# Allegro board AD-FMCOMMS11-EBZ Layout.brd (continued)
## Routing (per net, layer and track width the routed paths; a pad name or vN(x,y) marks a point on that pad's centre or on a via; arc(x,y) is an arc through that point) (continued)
SVDD12_DAC: length 54.2
  TOP w0.203: U1.K14 v2(54.48,23.34) U1.J14 ; U1.R1 57.22,16.53 v2(57.23,16.53)
  TOP w0.254: U1.M13 U1.M14 v2(56.22,23.34) ; v2(56.72,19.34) U1.P7 ; U1.K2 v2(54.48,17.34) U1.J2 ; U1.N2 v2(55.97,17.34) U1.M2 v2(55.72,17.84) ; U1.P3 v2(56.72,18.1) U1.P4 ; U1.P13 v2(56.72,22.6) U1.P12 ; U1.P9 v2(56.72,21.34)
  L3_SIGNAL w0.508: v3(59.82,16.72) v3(59.31,16.72) v3(58.8,16.72) 58.54,16.72 v3(58.29,16.47) 58.29,14.94 56.9,13.55 52.83,13.55 51.56,12.28 48.26,12.28 46.61,13.93 46.61,16.22 44.96,17.87 37.72,17.87 v3(36.96,18.63)
  BOTTOM w0.203: C133.1 56.22,23.73 v2(56.22,23.34)
  BOTTOM w0.254: v2(54.48,23.34) 54.48,23.76 C132.1 ; C115.1 57,17.82 v2(56.72,18.1) ; v2(56.72,22.6) 56.86,22.6 C121.1 ; C136.1 55.97,16.88 v2(55.97,17.34) ; v2(56.72,21.34) 57.01,21.34 C108.1
  BOTTOM w0.305: v2(57.23,16.53) C130.1 57.96,16.53 ; C111.1 56.72,19.47 v2(56.72,19.34) ; v3(36.96,18.63) 36.96,20.03 36.07,20.92 R45.1 ; v2(54.48,17.34) 54.48,17.01 C134.1
  BOTTOM w0.406: C335.1 57.52,14.97 ; C335.1 58.18,14.31 ; C335.1 57.52,13.65
  BOTTOM w0.508: C122.1 59.83,18.4 ; C122.1 59.83,17.08 ; C122.1 59.17,17.74
  BOTTOM w0.635: 58.57,15.58 C106.1 ; C106.1 59.47,16.53 ; C106.1 59.47,14.63 ; C311.1 59.47,14.25 ; C311.1 58.57,13.3 ; C311.1 59.47,12.34
  BOTTOM w0.762: 58.23,11.75 E9.2 59.16,10.76
  vias: v2(57.22,23.84)
SVDD12_EN: length 121
  TOP w0.203: U21.3 55.26,1.6 v3(54.61,2.25)
  L3_SIGNAL w0.203: v3(48.64,31.27) 49.42,31.27 49.91,31.76 60.38,31.76 61.7,30.44 64.01,30.44 v3(65.28,29.17)
  L10_SIGNAL w0.203: v3(65.28,29.17) 66.29,28.15 66.29,19.39 v3(68.96,16.72) 68.96,14.82 72.9,10.88 72.9,3.77 72.01,2.88 58.42,2.88 57.78,2.25 v3(54.61,2.25) ; v1(51.43,38.19) 51.43,33.23 49.47,31.27 v3(48.64,31.27) 47.56,31.27 44.2,27.9 v1(38.23,27.9)
  BOTTOM w0.203: R89.1 v1(51.43,38.19) ; U9.C1 68.19,18.25 68.96,17.49 v3(68.96,16.72) ; v1(38.23,27.9) 37.72,27.39 31.24,27.39 29.46,25.61 23.75,25.61 22.73,24.6 22.73,21.93 23.1,21.56 23.75,21.56 24.02,21.3 ; 24.02,21.3 U22.8 ; 24.02,21.3 24.01,21.3 R53.2
SVDD12PHY_DAC: length 15.8
  BOTTOM w0.305: v2(55.22,17.84) 55.22,19.16 55.4,19.33 ; 55.22,22.34 v2(55.22,22.84) 55.52,22.84 55.72,23.04 55.72,25.38 C340.1
  BOTTOM w0.508: 55.4,19.33 55.4,22.16 55.22,22.34
  BOTTOM w0.635: C313.1 59.94,26.5 59.31,25.87 55.99,25.87 C340.1
  BOTTOM w0.762: E6.2 58.04,27.33 C313.1
VDD5_361: length 14.3
  TOP w0.508: TP22.1 C164.1
  TOP w0.635: 39.74,63.69 39.74,63.82 39.71,63.84 ; 39.74,63.69 C164.1 ; 39.74,63.69 C157.1 ; v3(46.86,61.68) 46.61,61.94 TP22.1
  TOP w0.762: C157.1 39.71,63.84 39.81,63.94 E22.2
  BOTTOM w0.305: U19.4 45.47,61.3 45.78,60.98 C333.1 v3(46.86,61.68)
VDD_1119: length 10.4
  TOP w0.254: U25.2 26.81,52.15 26.54,52.41 26.54,52.54 26.29,52.79 25.97,52.79 R137.1
  TOP w0.305: C337.1 25.7,53.62 C338.1 25.02,53.11 ; 25.35,52.86 R137.1
  BOTTOM w0.508: C238.1 23.81,50.18 ; C238.1 23.15,49.52 ; C238.1 23.15,50.84
  BOTTOM w0.635: C233.1 23.37,49.1 ; C233.1 24.28,48.15 ; C233.1 23.37,47.2 ; 26.03,48.2 E27.2 25.04,47.27
  vias: v3(23.75,52.92) v3(24.38,52.92)
VDDA12_DAC: length 9.4
  TOP w0.305: TP1.1 v3(52.07,29.81)
  BOTTOM w0.305: E7.2 v3(52.07,29.81) ; v2(50.72,22.84) v2(50.72,23.34) 50.74,23.36 C135.1 50.74,24.9 C93.1
  BOTTOM w0.508: C93.1 50.66,26.48 C84.1
  BOTTOM w0.635: C84.1 50.8,26.92 50.8,29.74 E7.2
VDDA25_DAC: length 19.9
  TOP w0.305: TP4.1 v3(31.88,14.57)
  TOP w0.508: C1.1 39.37,22.83 v3(39.37,23.33) ; v3(43.05,20.15) v3(42.54,20.15) v4(41.91,20.15) v4(41.53,20.15) T1.2 v4(41.02,20.15) v3(40.39,20.15) 39.36,20.15 C3.1 ; v3(43.05,18.88) v4(42.67,18.88) v4(42.04,18.88) T1.1 v4(41.4,18.88) v4(40.89,18.88) v4(40.39,18.88) 39.5,18.88 39.37,18.76 ; v3(47.69,14.25) 47.69,13.77 C185.1 ; v3(47.83,15.84) C79.1
  BOTTOM w0.254: C109.1 49.47,21.74 v2(49.78,21.42) ; v2(49.78,18.88) 49.47,18.57 C112.1 ; v2(50.72,19.34) 50.72,19.63 C113.1 ; v2(50.72,20.84) 50.72,20.68 C114.1
  BOTTOM w0.508: R48.1 v3(36.2,18.63) ; 33.41,14.03 C96.1 32.75,14.69 ; v3(43.05,20.15) v3(42.54,20.15)
  BOTTOM w0.635: C87.1 33.06,13.74 ; C87.1 32.16,12.79 ; C87.1 33.06,11.83 ; 33.06,11.45 E12.2 32.16,10.5
  vias: v2(50.22,17.34) v2(50.72,22.34) v2(50.72,17.84) v2(51.22,23.84) v2(51.22,21.84) v2(51.22,18.34) v3(31.24,14.57) v3(31.24,13.93) v3(31.24,13.3) v3(31.88,13.93) v3(31.88,13.3) v3(39.37,19.39) v3(40.39,23.33) v3(42.54,23.2) v3(43.05,22.31) v3(43.05,21.42) v4(39.5,18.12) v4(39.88,17.61) v4(40.39,17.11) v4(41.02,23.33) v4(41.02,17.11) v4(41.53,23.33) v4(41.66,17.11) v4(42.04,23.33) v4(42.29,17.11) v4(42.93,17.11) v4(43.05,23.2) v4(43.05,20.79) v4(43.56,23.2) v4(43.56,17.11) v4(44.07,23.2) v4(44.2,17.11) v4(44.58,23.2) v4(44.83,17.11) v4(45.09,23.2) v4(45.34,17.11) v4(45.59,23.2) v4(45.97,17.11) v4(46.1,23.2) v4(46.61,23.2) v4(46.61,17.11) v4(47.12,23.2) v4(47.75,23.2) v4(47.88,17.23) v4(48.39,22.82) v4(48.39,17.49) v4(48.89,22.44) v4(48.89,17.87)
VDDA25_EN: length 30.4
  L10_SIGNAL w0.203: v3(34.67,1.87) 31.24,5.29 29.97,5.29 24.51,10.76 24.51,17.36 v3(24.13,17.74)
  BOTTOM w0.203: 23.75,20.39 23.1,20.39 22.86,20.15 22.86,19.01 v3(24.13,17.74) ; 23.75,20.39 25.13,20.39 25.53,20.8 U22.7 ; 23.75,20.39 R54.2 ; U7.7 35.06,2.25 v3(34.67,1.87)
VDDC12_DAC: length 15.5
  TOP w0.254: v2(52.72,16.84) v2(52.72,17.34) v2(52.72,17.84) ; v2(52.22,23.84) v2(52.72,23.84) v2(52.72,23.34) v2(52.72,22.84)
  TOP w0.305: TP3.1 v3(38.86,15.71)
  BOTTOM w0.203: v2(52.72,17.34) 52.25,17.34 C138.1 ; v2(52.72,17.34) v2(52.72,16.84) ; v2(52.72,17.34) v2(52.72,17.84)
  BOTTOM w0.254: C107.1 v2(52.29,21.3) ; C110.1 v2(52.2,18.88)
  BOTTOM w0.305: U28.11 40.51,14.33 ; U28.13 41.76,14.46 41.53,14.69 41.15,14.69 ; v2(52.72,23.84) 53.14,23.84 C137.1 ; 39,13.53 U28.9 39.51,14.33 ; U28.12 41.01,14.33 ; U28.10 40.01,14.33
  BOTTOM w0.508: C183.1 53.35,15.31 v3(53.21,15.45) 53.07,15.31 C184.1
  BOTTOM w0.635: 39.78,15.96 C341.1 40.68,15.01
  vias: v3(38.86,15.07) v3(39.5,15.71) v3(39.5,15.07)
VIN_N: length 2.8
  TOP w0.203: R63.2 45.52,52.74 45.88,52.38 U101.A10
VIN_P: length 2.8
  TOP w0.203: U101.A9 45.9,51.58 45.54,51.22 R62.2
3P3V_P1: length 22.2
  TOP w0.508: v3(94.28,9.03) 94.28,8.12 R40.2 ; v3(72.25,4.39) R30.2 73.52,3.39 R32.1
  TOP w1.016: 84.48,4.72 E3.1 ; E3.1 85.41,5.71 ; E3.1 85.41,3.73
  BOTTOM w0.305: 94.91,9.67 v3(94.28,9.03) ; 80.26,12.28 79.48,11.5 U6.18 79.99,10.85 ; 81.08,10.1 U6.19 80.23,10.61 ; 81.65,9.6 81.15,9.1 U6.21 ; 81.65,9.6 U6.20 ; 81.65,9.6 v3(81.66,9.61) ; 94.91,14.75 v1(94.3,14.44)
  BOTTOM w0.406: 94.91,12.21 v3(94.28,11.57) ; P1.C39 v3(96.82,11.57)
  BOTTOM w0.508: R28.1 84.07,9.36 84.2,9.49 v3(84.2,9.61)
  BOTTOM w0.762: 83.06,9.81 C56.2 ; C56.2 81.9,10.82 ; C56.2 84.21,10.82 ; 81.22,13.08 C57.2 80.26,12.28
  vias: v3(82.3,9.61) v3(82.93,9.61) v3(83.57,9.61) v3(85.09,6.56) v3(85.09,5.93) v3(85.09,3.52) v3(85.09,2.88) v3(85.72,6.56) v3(85.72,5.93) v3(85.72,3.52) v3(85.72,2.88)
3P3VAUX_P1: length 62.3
  TOP w0.305: U26.16 103.52,10.64 v3(103.25,10.37) ; v3(102.81,20.15) 102.81,20.94 R34.2 ; U26.10 103.52,15.69 103.11,16.1 C129.2 ; U26.17 v3(104.02,10.37) ; R64.2 v3(104.15,3.53)
  TOP w0.508: C154.1 v3(102.81,20.15) ; v3(102.73,31.7) 102.98,31.44 C83.1 102.98,30.17 102.87,30.06 U8.8
  TOP w0.635: C154.1 103.11,18.58 C129.2
  L10_SIGNAL w0.305: v3(104.15,3.53) 104.65,4.02 104.65,9.75 v3(104.02,10.37)
  L10_SIGNAL w0.508: v3(103.25,10.37) v3(104.02,10.37) ; v3(103.25,10.37) 103.25,11.74 102.81,12.19 v3(102.81,20.15) 104.13,20.15 105.03,21.05 105.03,26 102.73,28.29 v3(102.73,31.7) ; v3(103.25,10.37) 100.91,10.37 100.51,10.78 100.51,11.85 99.63,12.72 99.63,14.86 99.1,15.38 94.87,15.38 93.73,16.53 93.73,18.64 v1(94.28,19.19)
  BOTTOM w0.508: 94.91,19.83 v1(94.28,19.19)
+INTERNAL_CLK: length 4.1
  BOTTOM w0.305: Y1.4 24.74,36.79 R33.2 R73.1 28.32,36.79 JP1.1
-INTERNAL_CLK: length 4.1
  BOTTOM w0.305: JP2.1 28.32,34.25 R12.1 R10.2 24.74,34.25 Y1.5
ADC_CLK_N: length 2.8
  TOP w0.203: U101.G14 52.81,56.02 53.62,56.83 R70.2 53.62,57.99 C201.2
ADC_CLK_P: length 2.8
  TOP w0.203: U101.F14 52.01,56.02 51.21,56.83 R69.1 51.21,58.04 C202.2
ARST: length 1.9
  TOP w0.305: U101.L9 v1(56.01,51.83)
  BOTTOM w0.203: v1(56.01,51.83) 56.45,51.4 56.81,51.4 R104.1
BST_2165: length 2.8
  TOP w0.203: C61.2 75.44,9.14 75.44,8.98 v3(75.06,8.6)
  BOTTOM w0.203: v3(75.06,8.6) 75.06,8.6 U6.9
BST_2384: length 3.7
  TOP w0.203: C39.2 78.57,32.98 v3(79.12,32.98)
  BOTTOM w0.305: U2.15 78.99,32.85 v3(79.12,32.98)
CSB1119: length 97
  TOP w0.203: v3(33.15,53.81) 33.15,53.3 31.49,51.65 U25.16 ; U23.13 107.04,53.28 v3(108.08,54.32)
  L3_SIGNAL w0.203: v3(33.15,53.81) 33.7,54.36 33.7,57.17 35.17,58.63 39.75,58.63 43.49,62.37 69.78,62.37 71.37,63.97 80.9,63.97 81.91,64.98 86.36,64.98 88.65,62.7 88.65,61.43 90.93,59.14 95.76,59.14 99.31,62.7 v3(103.38,62.7)
  L10_SIGNAL w0.203: v3(108.08,54.32) 108.08,57.49 103.38,62.19 v3(103.38,62.7)
CSB1119_FMC: length 23.7
  TOP w0.203: v3(102.62,54.19) 103.25,54.19 103.72,53.72 U23.2
  L10_SIGNAL w0.203: v3(102.62,54.19) 96.39,54.19 93.22,51.01 93.22,48.47 92.33,47.58 92.33,43.19 91.12,41.98 v1(90.54,41.98)
  BOTTOM w0.127: P1.G15 v1(90.54,41.98)
CSB4355: length 95.2
  TOP w0.203: v3(108.08,52.79) 108.07,52.78 U23.12
  L3_SIGNAL w0.203: v3(108.08,52.79) 107.19,53.68 100.23,53.68 100.1,53.81 65.53,53.81 61.47,57.87 49.28,57.87 48.01,56.6 v3(36.83,56.6)
  L10_SIGNAL w0.203: v3(36.83,56.6) 36.83,49.49 36.45,49.11 36.45,47.46 36.96,46.95 36.96,40.6 v1(36.45,40.09)
  BOTTOM w0.203: U18.3 37.35,38.81 36.45,39.71 v1(36.45,40.09)
CSB4355_FMC: length 23.3
  TOP w0.203: v3(102.62,53.17) 103,52.78 U23.3
  L10_SIGNAL w0.203: v1(90.48,39.53) 90.49,39.53 92.33,41.36 92.33,42.25 95.76,45.68 97.03,45.68 97.92,46.57 100.87,46.57 102.62,48.32 v3(102.62,53.17)
  BOTTOM w0.127: P1.G16 v1(90.48,39.53)
CSB5240: length 146.7
  TOP w0.203: v3(108.08,51.27) 107.06,52.28 U23.11
  TOP w0.229: U16.29 16,19.9 v3(15.75,20.15)
  L3_SIGNAL w0.203: v3(22.35,54.19) 27.56,59.4 37.72,59.4 38.1,59.78 39.82,59.78 43.56,63.52 54.29,63.52 54.86,64.1 70.66,64.1 71.17,64.6 78.74,64.6 79.76,65.62 86.49,65.62 89.15,62.95 89.15,61.68 91.19,59.65 95.38,59.65 99.62,63.9 v3(103.32,63.9)
  L10_SIGNAL w0.203: v3(108.08,51.27) 107.44,51.9 107.44,57.24 102.66,62.02 102.66,63.24 v3(103.32,63.9) ; v3(15.75,20.15) 16.64,21.04 16.64,41.62 23.24,48.22 23.24,53.3 v3(22.35,54.19)
CSB5240_FMC: length 11.1
  TOP w0.203: v3(102.11,51.9) 102.49,52.28 U23.4
  L10_SIGNAL w0.203: v3(102.11,51.9) 101.15,50.94 98.61,50.94 96.52,48.86 96.52,47.15 v1(96.5,47.13)
  BOTTOM w0.203: P1.C10 v1(96.5,47.13)
CSB9162: length 83.4
  TOP w0.203: U24.11 107.82,45.43 108.08,45.17 v3(108.08,44.54) ; U1.G15 53.22,24.08 52.32,24.98 v1(52.32,25.49)
  L3_SIGNAL w0.203: v1(52.32,25.49) 52.52,25.29 53.77,25.29 54.88,26.4 59.92,26.4 63.25,23.07 75.82,23.07 77.6,21.3 91.68,21.3 93.26,22.88 93.26,24.27 95.42,26.43 98.34,26.43 98.85,25.92 101.01,25.92 101.9,25.04 103.69,25.04 v3(104.27,25.61)
  BOTTOM w0.203: v3(104.27,25.61) 104.27,26.76 107.23,29.72 107.23,35.35 107.19,35.39 107.19,38.57 108.08,39.46 v3(108.08,44.54)
CSB9162_FMC: length 13.3
  TOP w0.203: v3(102.49,45.17) 102.74,45.43 U24.4
  L3_SIGNAL w0.203: v3(102.49,45.17) 101.78,45.88 v1(99.82,45.88)
  BOTTOM w0.203: P1.G12 91.76,45.88 v1(99.82,45.88)
CSB9625: length 62.7
  TOP w0.203: U23.10 106.93,51.78 107.19,51.52 107.19,50.63 v3(108.08,49.74) ; U101.G4 v1(53.21,47.98)
  L3_SIGNAL w0.203: v3(108.08,49.74) 108.08,50.51 106.05,52.54 100.36,52.54 99.56,53.33 60.1,53.33 56.13,49.36 54.6,49.36 v1(53.21,47.98)
CSB9625_FMC: length 11.7
  TOP w0.203: v3(102.11,50.76) 103.13,51.78 U23.5
  L10_SIGNAL w0.203: v1(95.87,47.13) 95.87,46.79 96.11,46.54 96.8,46.54 97.1,46.85 97.1,47.79 98.93,49.62 100.97,49.62 v3(102.11,50.76)
  BOTTOM w0.203: P1.C11 v1(95.87,47.13)
DAC_CLK_N: length 2.4
  TOP w0.127: U1.D1 51.72,16.58 51.6,16.45 51.6,14.88 C190.2
DAC_CLK_P: length 2.4
  TOP w0.127: U1.C1 51.22,16.58 51.34,16.45 51.34,14.88 C191.2
DAC_OUT_N: length 0.3
  TOP w0.229: U1.A7 49.91,19.77
DAC_OUT_P: length 0.3
  TOP w0.229: U1.A8 49.91,20.41
DIVCLK_N: length 36.8
  TOP w0.127: v1(75.23,55.31) 74.96,55.59 60.22,55.59 59.69,55.05 58.69,55.05 U101.P13 ; v1(80.14,54.32) 80.64,54.32 80.76,54.44 92.09,54.44 93,53.53 93.34,53.53 C240.1
  BOTTOM w0.127: v1(75.23,55.31) 75.51,55.59 79.25,55.59 80.14,54.69 v1(80.14,54.32)
DIVCLK_P: length 37.3
  TOP w0.127: v1(75.23,56.12) 74.96,55.84 63.47,55.84 63.17,56.14 62.86,56.14 62.56,55.84 62.25,55.84 61.95,56.14 61.64,56.14 61.34,55.84 61.03,55.84 60.73,56.14 60.42,56.14 59.58,55.31 58.69,55.31 U101.P14 ; C239.1 93.34,53.81 93.08,53.81 92.19,54.7 80.78,54.7 80.65,54.82 v1(80.64,54.82)
  BOTTOM w0.127: v1(80.64,54.82) 80.37,54.82 79.35,55.84 75.51,55.84 v1(75.23,56.12)
DOUTA_N: length 53.5
  TOP w0.127: U101.P10 58.47,52.44 59.03,52.44 59.18,52.28 59.44,52.28 59.56,52.41 59.56,52.65 59.44,52.77 59.44,53.04
  TOP w0.254: 59.44,53.04 60.08,53.68 60.58,53.68 60.85,53.41 61.19,53.41 61.47,53.68 61.98,53.68 62.23,53.43 62.61,53.43 62.86,53.68 63.37,53.68 63.63,53.43 64.13,53.43 64.39,53.68 64.77,53.68 65.02,53.43 65.53,53.43 65.79,53.68 76.59,53.68 79.77,56.86 92.16,56.86 94.75,59.45 99,59.45 100.63,57.81 100.63,54.68 99.92,53.97 97.99,53.97 C223.1
DOUTA_P: length 54.4
  TOP w0.127: 59.12,53.36 59.1,53.35 59.1,53.26 58.61,52.77 58.29,52.77 U101.N10
  TOP w0.254: C222.1 97.99,53.52 100.11,53.52 101.09,54.49 101.09,58 99.19,59.9 94.56,59.9 91.97,57.31 79.58,57.31 76.4,54.14 59.89,54.14 59.12,53.36
DOUTB_N: length 40.6
  TOP w0.127: 60.41,52.05 60.39,52.03 60.3,52.03 60.12,51.85 59.85,51.58 U101.P9
  TOP w0.254: 60.41,52.05 60.64,52.28 60.93,52.28 61.13,52.09 61.51,52.09 61.71,52.28 77.23,52.28 80.4,55.46 93.09,55.46 93.69,56.06 96.93,56.06 C209.1
DOUTB_P: length 41.5
  TOP w0.127: 60.09,52.38 60.07,52.35 60.07,52.27 59.71,51.91 58.95,51.91 58.88,51.98 58.29,51.98 U101.N9
  TOP w0.254: C208.1 96.93,56.51 93.5,56.51 92.9,55.92 80.21,55.92 77.04,52.74 60.45,52.74 60.09,52.38
DOUTC_N: length 40.8
  TOP w0.127: 61.17,50.94 61.14,50.94 61.08,51 60.86,51 60.72,50.86 58.5,50.86 U101.P8
  TOP w0.254: 61.17,50.94 78.29,50.94 80.78,53.43 91.61,53.43 94.31,50.72 96.93,50.72 C211.1
DOUTC_P: length 41.7
  TOP w0.127: 61.17,51.4 61.14,51.4 61.08,51.33 60.72,51.33 60.58,51.19 58.29,51.19 U101.N8
  TOP w0.254: C210.1 96.93,51.18 94.5,51.18 91.8,53.88 80.59,53.88 78.1,51.4 61.17,51.4
DOUTD_N: length 40.5
  TOP w0.127: U101.P7 58.51,50.08 58.91,50.08 59.41,49.58 59.51,49.58 59.55,49.54 59.55,49.53
  TOP w0.254: C213.1 96.93,45.64 86.53,45.64 82.64,49.53 59.55,49.53
DOUTD_P: length 41.4
  TOP w0.127: U101.N7 58.04,50.41 59.05,50.41 59.33,50.13 59.53,49.93 59.71,49.93 59.76,49.98
  TOP w0.254: 59.76,49.98 82.83,49.98 86.71,46.1 96.93,46.1 C212.1
DOUTE_N: length 39.5
  TOP w0.127: U101.P5 58.81,48.38 58.88,48.45 59.64,48.45 59.88,48.21 60.36,48.21 60.42,48.14 60.45,48.14
  TOP w0.254: 60.45,48.14 81.99,48.14 85.8,44.33 91.64,44.33 92.88,43.1 95.66,43.1 C219.1
DOUTE_P: length 40.4
  TOP w0.127: 60.45,48.6 60.42,48.6 60.36,48.54 60.02,48.54 59.78,48.78 58.22,48.78 U101.N5
  TOP w0.254: C218.1 95.66,43.56 93.06,43.56 91.83,44.79 91.32,44.79 85.99,44.79 82.18,48.6 60.45,48.6
DOUTF_N: length 41.5
  TOP w0.127: 59.81,47.08 59.8,47.1 59.8,47.18 59.74,47.24 59.41,47.58 U101.P4
  TOP w0.254: C215.1 90.49,40.52 89.16,41.85 86.25,41.85 81.28,46.82 60.07,46.82 59.81,47.08
DOUTF_P: length 42.4
  TOP w0.127: U101.N4 58.19,47.97 59.49,47.97 60.04,47.41 60.13,47.41
  TOP w0.254: C214.1 96.89,40.98 90.68,40.98 89.35,42.31 86.44,42.31 81.47,47.28 60.26,47.28 60.13,47.41
DOUTG_N: length 40.9
  TOP w0.127: 60.5,45.45 60.49,45.45 60.42,45.52 60.14,45.52 58.88,46.78 U101.P3
  TOP w0.254: 60.5,45.45 80.62,45.45 88.05,38.02 95.66,38.02 C221.1
DOUTG_P: length 41.9
  TOP w0.127: 60.5,45.91 60.45,45.85 60.27,45.85 58.94,47.18 58.2,47.18 U101.N3
  TOP w0.254: 60.5,45.91 80.81,45.91 88.24,38.48 95.66,38.48 C220.1
DOUTH_N: length 43.6
  TOP w0.127: 59.77,44.74 59.74,44.76 59.74,44.85 58.62,45.98 U101.P2
  TOP w0.254: C217.1 96.93,35.48 87.53,35.48 86.46,36.55 86.46,37.57 80,44.03 60.48,44.03 59.77,44.74
DOUTH_P: length 44.5
  TOP w0.127: U101.N2 58.03,46.39 58.67,46.39 59.98,45.09 60.07,45.09 60.09,45.06
  TOP w0.254: C216.1 96.93,35.94 87.72,35.94 86.92,36.74 86.92,37.76 80.19,44.49 60.67,44.49 60.09,45.06
DRST: length 2.5
  TOP w0.305: U101.M13 v1(56.56,55.03)
  BOTTOM w0.305: R103.2 56.01,55.59 v1(56.56,55.03)
DRVDD1P3_ADC: length 13.5
  TOP w0.305: TP11.1 v3(65.28,60.03) ; U101.N1 v1(58.01,44.78) U101.P1 58.41,45.17 v1(58.8,44.78) ; v1(58.8,49.18) U101.P6 v1(58.01,49.18) U101.N6 ; U101.P11 v1(58,53.18) U101.N11 v1(57.21,53.18) U101.M11
  BOTTOM w0.305: C271.1 57.98,44.74 v1(58.01,44.78) ; v1(57.21,53.18) 56.97,53.18 C276.1
  BOTTOM w0.508: C235.1 63.77,60.67 ; C235.1 63.11,60.01 ; C235.1 63.11,61.33 ; 63.59,59.71 C230.1 64.49,58.76
  BOTTOM w0.762: 66.48,58.53 E24.2 ; E24.2 65.56,59.52 ; E24.2 66.48,60.51
  vias: v3(64.01,60.03) v3(64.64,60.03) v3(65.28,59.4)
DRVDD2P5_ADC: length 11.9
  TOP w0.305: U101.N13 v1(57.9,55.07) 57.61,55.35 U101.N14 v1(58.01,55.98)
  TOP w0.508: TP18.1 58.17,42.23 ; TP18.1 58.17,40.75 ; TP18.1 58.9,41.49 ; C254.1 59.96,42.15 ; C254.1 59.3,41.49 ; C254.1 59.96,40.83
  TOP w0.635: C251.1 59.22,40.54 ; C251.1 58.32,39.58 ; C251.1 59.22,38.63 ; 58.93,38.29 E28.2 57.94,37.36
  BOTTOM w0.305: C260.1 57.98,56.02 v1(58.01,55.98) 57.98,55.94 C263.1 57.98,55.14 v1(57.9,55.07)
  vias: v3(58.04,43.01) v3(58.04,42.38) v3(58.69,43.01) v3(58.67,42.38)
DSYNC_P1_N: length 11.8
  TOP w0.127: v1(89.48,50.94) 89.69,51.15 89.69,51.51 89.55,51.65 89.23,51.65 88.98,51.4 88.72,51.4 88.47,51.65 88.21,51.65 87.96,51.4 87.71,51.4 87.45,51.65 81.84,51.65 v1(81.55,51.36)
  BOTTOM w0.127: R125.1 80.3,51.65 81.26,51.65 v1(81.55,51.36) ; P1.H8 v1(89.48,50.94)
DSYNC_P1_P: length 11.8
  TOP w0.127: v1(81.55,52.17) 81.82,51.9 89.65,51.9 89.94,51.61 89.94,51.19 v1(90.19,50.94)
  BOTTOM w0.127: R123.1 80.3,51.9 81.29,51.9 v1(81.55,52.17) ; P1.H7 v1(90.19,50.94)
DUT_DSYNC_N: length 26.5
  TOP w0.254: U101.L3 v1(56.41,46.38)
  BOTTOM w0.127: v1(56.41,46.38) 56.41,46.97 57.03,47.59 68.2,47.59 72.45,51.84 78.21,51.84 78.59,51.46 R124.2 78.88,51.65 79.21,51.65 R125.2
DUT_DSYNC_P: length 26.6
  TOP w0.254: U101.L4 v1(55.61,47.18)
  BOTTOM w0.127: v1(55.61,47.18) 56.26,47.18 56.92,47.84 68.09,47.84 72.35,52.09 R124.1 78.88,51.9 79.21,51.9 R123.2
FB_2384: length 4.7
  TOP w0.254: v3(72.77,31.46) 71.97,31.46 R15.2 R16.2
  BOTTOM w0.254: v3(72.77,31.46) 73.42,31.85 U2.2
FPGA_CLK_N: length 78.2
  TOP w0.127: v1(85.98,33.74) 86.26,33.46 95.05,33.46 C34.1 ; T6.4 23.88,35.14 24.19,34.82 24.19,34.19 24.38,34 25.68,34 26.95,35.27 27.43,35.27 v1(27.69,35.52)
  L3_SIGNAL w0.127: v1(85.98,33.74) 85.72,33.49 84.71,33.49 82.17,30.95 71.99,30.95 71.22,31.71 71.01,31.71 66.29,31.71 63.63,34.38 63.42,34.38 41.15,34.38 39.75,32.98 31.22,32.98 28.81,35.39 27.81,35.39 v1(27.69,35.52)
FPGA_CLK_P: length 78.2
  TOP w0.127: T6.6 23.88,32.6 24.19,32.92 24.19,33.55 24.38,33.74 25.78,33.74 27.05,35.01 27.56,35.01 v1(27.69,34.89) ; C32.1 95.07,33.21 86.21,33.21 v1(85.98,32.98)
  L3_SIGNAL w0.127: v1(27.69,34.89) 27.94,35.14 28.7,35.14 31.11,32.73 39.86,32.73 41.25,34.12 63.52,34.12 66.19,31.46 71.12,31.46 71.88,30.69 82.27,30.69 84.81,33.23 85.72,33.23 v1(85.98,32.98)
GA0_P1: length 18.2
  TOP w0.203: v3(101.3,14.95) 102.19,14.95 102.5,14.63 U26.11 ; U8.2 v3(104.14,21.86)
  L3_SIGNAL w0.203: v1(96.59,16.65) 97.03,16.22 100.03,16.22 v3(101.3,14.95)
  L10_SIGNAL w0.203: v3(101.3,14.95) 101.6,15.25 101.6,20.42 103.04,21.86 v3(104.14,21.86)
  BOTTOM w0.254: P1.C34 v1(96.59,16.65)
GA1_P1: length 20.7
  TOP w0.203: v3(103.93,20.97) 102.87,22.03 U8.1 ; U26.13 101.68,13.3 v3(101.3,13.68)
  L10_SIGNAL w0.203: v3(101.3,13.68) 102.11,14.49 102.11,20.29 102.79,20.97 v3(103.93,20.97)
  BOTTOM w0.203: v3(101.3,13.68) 99.6,15.38 95.55,15.38 94.91,16.02
IRQ9162: length 68.9
  TOP w0.203: v3(103.17,33.67) 103.17,33.16 103.6,32.73 U14.8
  L3_SIGNAL w0.203: v2(53.22,16.84) 53.6,16.84 54.69,15.76 57.38,15.76 57.66,16.04 57.66,16.85 58.29,17.49 84.63,17.49 v1(86.34,19.19)
  L10_SIGNAL w0.203: v3(103.17,33.67) 95.43,33.67 91.82,30.06 91.82,28.15 86.34,22.67 v1(86.34,19.19) ; v1(53.59,12.91) 54.1,13.42 54.1,16.34 53.6,16.84 v2(53.22,16.84)
  BOTTOM w0.203: v1(53.59,12.91) CR5.C
IRQ9162_FMC: length 21.8
  TOP w0.203: v3(106.55,33.76) 106.03,33.23 U14.3
  L3_SIGNAL w0.203: v1(89.21,39.53) 89.92,38.82 91.16,38.82 94.84,35.14 103.5,35.14 104.89,33.76 v3(106.55,33.76)
  BOTTOM w0.203: P1.H16 v1(89.21,39.53)
IRQ9625: length 76.4
  TOP w0.203: U13.11 106.92,37.56 107.19,37.3 107.19,35.6 v3(106.72,35.14)
  TOP w0.254: U101.H5 v1(54.01,47.98)
  L3_SIGNAL w0.203: v1(54.01,47.98) 54.65,47.98 54.81,47.81 86.54,47.81 89.04,50.32 95.31,50.32 96.39,51.4 106.43,51.4 107.31,50.51 107.31,49.49 v3(108.08,48.73)
  L10_SIGNAL w0.203: v3(108.08,48.73) 106.43,47.08 106.43,42.12 106.68,41.87 106.68,40.47 106.43,40.22 106.43,35.44 v3(106.72,35.14)
  BOTTOM w0.203: R79.2 54.5,48.16 54.32,47.98 v1(54.01,47.98)
IRQ9625_FMC: length 14
  TOP w0.203: v3(102.74,36.54) 102.74,37.16 103.14,37.56 U13.6
  L10_SIGNAL w0.203: v3(102.74,36.54) 101.19,36.54 99.99,37.74 97.07,37.74 94.6,40.21 v1(94.6,42.05)
  BOTTOM w0.203: 94.91,41.42 v1(94.6,42.05)
MUX_OUT: length 89.8
  TOP w0.203: v3(106.17,40.73) 107.44,40.73 TP20.1 108.08,39.97 107.18,39.06 U13.14 ; R11.2 v1(33.27,44.03)
  L3_SIGNAL w0.203: v3(34.73,36.47) 36.32,38.06 40.64,38.06 41.91,36.79 51.43,36.79 52.39,37.74 63.82,37.74 65.79,39.71 85.34,39.71 85.85,40.22 94.73,40.22 95.24,40.73 101.09,40.73 102.23,39.58 105.03,39.58 v3(106.17,40.73)
  L10_SIGNAL w0.203: v3(34.73,36.47) 33.27,37.93 v1(33.27,44.03)
  BOTTOM w0.203: U18.30 34.94,36.27 v3(34.73,36.47)
MUXOUT_FMC: length 10.9
  TOP w0.203: v3(102.49,40.22) 102.49,39.46 102.88,39.06 U13.3
  L3_SIGNAL w0.203: v3(102.49,40.22) 101.35,41.36 95.89,41.36 95.23,42.02 v1(95.23,42.05)
  BOTTOM w0.305: 94.91,42.69 v1(95.23,42.05)
PG_1184: length 272.3
  TOP w0.203: R13.1 62.5,11.64 62.5,10.89 v3(62.48,10.88) ; v3(25.91,62.95) 25.91,63.84 25.65,64.1 U3.6 ; R75.1 87.76,66.7 87.76,65.62 89.83,63.54 v3(89.83,61.81) ; v3(66.8,29.11) R83.1 ; R31.1 69.66,3.39 R30.1 v3(71.26,4.39)
  L3_SIGNAL w0.203: v3(62.48,10.88) 61.72,11.64 59.94,11.64 58.55,10.25 v3(43.75,10.25) 41.78,12.22 41.78,15.58 40.51,16.85 30.1,16.85 v3(29.34,17.61) ; v3(76.2,28.66) 75.69,28.15 67.75,28.15 v3(66.8,29.11) ; v3(75.06,7.83) 73.28,7.83 71.26,5.81 v3(71.26,4.39) ; v3(89.83,61.81) 89.83,63.16 86.74,66.25 78.36,66.25 v3(77.34,65.24) ; v3(32.64,63.59) 32,62.95 v3(25.91,62.95) ; v3(76.2,23.96) 78.35,21.8 91.31,21.8 92.58,23.07 92.58,24.61 94.91,26.94 97.58,26.94 98.34,27.7 100.5,27.7 101.52,26.69 102.02,26.69 102.36,27.02 102.36,27.77 v3(101.73,28.41)
  L10_SIGNAL w0.203: v3(62.48,10.88) 62.48,7.96 63.88,6.56 69.09,6.56 v3(71.26,4.39) ; v3(75.06,7.83) 76.2,8.97 v3(76.2,23.96) v3(76.2,28.66) ; v3(29.34,17.61) 29.34,32.9 28.45,33.79 28.45,43.27 25.91,45.81 v3(25.91,62.95)
  BOTTOM w0.203: v3(62.48,10.88) 62.73,11.13 U5.3 ; v3(77.34,65.24) 77.03,64.92 R72.1 ; U22.6 28.81,20.3 29.34,19.77 v3(29.34,17.61) ; R76.1 34.29,54.95 32.64,56.6 v3(32.64,63.59) ; v3(89.83,61.81) 91.68,59.96 94.79,59.96 95.29,60.47 99.99,60.47 101.22,59.24 101.22,28.92 v3(101.73,28.41) ; U6.8 75.32,8.1 v3(75.06,7.83) ; R85.1 v3(43.75,10.25)
  BOTTOM w0.254: v3(76.2,28.66) U2.21
PG_C2M_P1: length 206.9
  L3_SIGNAL w0.203: v3(101.73,27.27) 100.78,28.21 92.39,28.21 86.49,22.31 78.74,22.31 v3(77.09,23.96) 75.44,25.61 66.17,25.61 v3(64.64,24.09) 61.47,27.27 58.47,27.27 57.84,27.9 54.02,27.9 52.11,26 35.05,26 34.16,25.11 v1(31.5,25.11)
  L10_SIGNAL w0.203: v3(77.22,29.04) 76.71,28.54 76.71,24.34 v3(77.09,23.96) 76.71,23.58 76.71,13.68 81.28,9.1 v3(81.28,7.83) ; v3(64.64,24.09) v3(64.64,16.72) ; v3(23.5,66.89) 26.67,63.71 26.67,50.76 30.35,47.08 30.35,40.32 32.18,38.5 32.18,36 31.5,35.32 31.5,31.43 31.88,31.05 31.88,25.49 v1(31.5,25.11)
  BOTTOM w0.203: R68.1 22.97,66.89 v3(23.5,66.89) ; U5.6 64.9,13.55 64.64,13.8 v3(64.64,16.72) ; R96.1 34.29,24.36 R95.1 34.24,24.28 R91.1 33.02,24.73 32.64,25.11 v1(31.5,25.11) ; v3(81.28,7.83) 81.01,8.1 U6.23 ; P1.D1 95.68,59.96 99.74,59.96 100.71,58.99 100.71,28.28 v3(101.73,27.27)
  BOTTOM w0.254: v3(77.22,29.04) 76.7,29.56 U2.20
PLL_REF_IN_N: length 1.5
  BOTTOM w0.254: U18.28 34.36,35.27 C186.2
PLL_REF_IN_P: length 1.5
  BOTTOM w0.254: C187.2 34.36,35.77 U18.29
PWDN: length 0.6
  TOP w0.254: U101.K4 v1(54.81,47.18)
RBIAS_EXT: length 1
  TOP w0.254: U101.J6 v1(54.81,48.78)
  BOTTOM w0.254: v1(54.81,48.78) 54.8,48.79 R110.2
REXT: length 1.2
  TOP w0.305: U101.M12 v1(57.21,54.38)
  BOTTOM w0.305: v1(57.21,54.38) 57.02,54.38 R109.2
RF_VDD_AMP_5: length 16.1
  TOP w0.305: C20.1 20.32,14.71 ; C20.1 19.66,14.04 ; C20.1 20.98,14.04 ; 17.05,17.7 U16.1 17.55,16.88 17.27,16.6 ; 18.36,13.87 C21.1 ; C21.1 18.92,14.38 ; C21.1 19.48,13.87 ; 21.21,14.46 L7.2 ; U16.25 17.12,21.9 17.55,22.34 U16.24 17.05,22.6 ; U16.25 16.54,21.9 16.19,22.25 C9.1 15.37,21.74 ; U16.25 16.85,22.41
  TOP w0.635: C102.1 16,16.19 ; C102.1 15.05,15.29 ; C102.1 16.96,15.29
  TOP w0.762: 12.6,15.52 E15.2 ; E15.2 13.59,16.45 ; E15.2 14.58,15.52
RST_B: length 1.2
  TOP w0.254: U101.K3 v1(55.61,46.38)
  BOTTOM w0.254: R101.2 55.88,45.98 55.61,46.25 v1(55.61,46.38)
RT_2165: length 7.1
  BOTTOM w0.203: U6.2 78.97,6.84 78.97,6.06 ; 78.97,6.06 78.99,6.06 79.12,5.93 79.76,5.93 80.28,5.41 C59.2 80.9,7.33 80.63,7.6 U6.24 ; 78.97,6.06 78.83,5.92 78.63,5.92 78.48,6.06 U6.3
SCL_P1: length 30.3
  TOP w0.203: v3(101.3,11.14) 101.81,11.64 102.3,11.64 102.5,11.85 U26.15 ; U8.6 v3(105.41,26.63)
  L3_SIGNAL w0.203: v3(105.41,26.63) 105.41,25.5 104.18,24.27 98.09,24.27 v3(96.82,23)
  L10_SIGNAL w0.203: v3(96.82,23) 101.09,18.73 101.09,15.71 100.71,15.33 100.71,13.29 100.96,13.04 101.47,13.04 101.85,12.66 101.85,11.69 v3(101.3,11.14)
  BOTTOM w0.203: P1.C30 v3(96.82,23)
SCLK_2P5: length 87.1
  TOP w0.203: U1.J13 54.22,22.46 v2(54.22,22.46) ; U24.13 106.92,46.43 v3(108.08,47.59)
  L3_SIGNAL w0.203: v3(105.92,21.3) 105.92,20.15 104.7,18.94 99.74,18.94 98.98,19.7 97.86,19.7 97.28,20.28 58.88,20.28 58.29,20.86 55.8,20.86 54.22,22.45 54.22,22.46 v2(54.22,22.46)
  L10_SIGNAL w0.203: v3(105.92,21.3) 106.55,20.66 107.19,20.66 107.57,21.04 107.57,33.62 107.95,34 107.95,36.03 107.44,36.54 107.44,38.71 108.12,39.39 108.12,43.48 107.54,44.05 107.54,47.05 v3(108.08,47.59)
SCLK_3P3: length 169.4
  TOP w0.127: U101.H4 53.21,47.18 53.21,43.9 v3(52.96,43.65)
  TOP w0.203: U13.13 108.07,38.56 v3(108.08,38.57) ; v3(32.26,53.81) 32.26,52.92 31.48,52.15 U25.17
  TOP w0.229: v3(15.75,18.63) 16.02,18.9 U16.31
  L3_SIGNAL w0.203: v1(36.45,40.85) 41.4,40.85 43.43,38.82 44.58,38.82 45.34,38.06 50.42,38.06 51.69,39.33 51.69,42.38 v3(52.96,43.65) 53.47,44.16 82.17,44.16 83.64,42.69 93.64,42.69 93.97,43.01 107.57,43.01 108.08,42.5 v3(108.08,38.57)
  L10_SIGNAL w0.203: v1(36.45,40.85) 35.94,40.35 35.94,39.84 36.26,39.52 36.64,39.52 36.96,39.2 36.96,38.06 35.81,36.92 35.81,36.08 32.94,33.2 32.94,25.42 33.4,24.95 33.4,19.9 29.97,16.47 v3(29.97,12.15)
  BOTTOM w0.203: v3(32.26,53.81) 31.11,52.67 31.11,50.38 30.1,49.36 30.1,43.27 32.13,41.24 36.07,41.24 v1(36.45,40.85) 35.94,40.35 35.94,38.7 36.35,38.29 U18.1 ; v3(29.97,12.15) 30.48,11.64 30.48,10.12 29.34,8.98 23.62,8.98 22.61,9.99 22.61,12.41 16.38,18.63 v3(15.75,18.63)
SCLK_FMC: length 21.2
  TOP w0.203: v3(102.5,38.58) 102.51,38.56 U13.4 ; U24.2 103.01,46.43 v3(102.49,46.95)
  L10_SIGNAL w0.203: v3(102.5,38.58) 103.12,39.2 103.12,40.85 102.62,41.36 102.62,42.67 103,43.05 103,46.44 v3(102.49,46.95) 100.71,45.17 100.71,44.28 99.57,43.14 97.59,43.14 v1(96.5,42.05)
  BOTTOM w0.203: P1.C14 v1(96.5,42.05)
SDA_P1: length 33.6
  TOP w0.203: U8.5 v3(106.68,26.63) ; U26.14 101.69,12.79 v3(101.3,12.41)
  L3_SIGNAL w0.203: v3(106.68,26.63) 106.05,26 106.05,25.12 104.44,23.51 100.04,23.51 98.9,22.37 96.18,22.37 v3(95.55,23)
  L10_SIGNAL w0.203: v3(101.3,12.41) 100.84,12.41 100.2,13.04 100.2,15.84 100.58,16.22 100.58,18.22 98.98,19.83 97.45,19.83 95.55,21.73 v3(95.55,23)
  BOTTOM w0.203: P1.C31 95.55,21.73 v3(95.55,23)
SDIO_2P5: length 64.2
  TOP w0.203: U14.9 103.09,32.23 v3(102.66,32.66)
  L3_SIGNAL w0.203: v3(100.84,24.91) 100.33,25.42 98.85,25.42 98.34,24.91 95.42,24.91 94.91,24.4 94.91,23.65 92.05,20.79 64.26,20.79 59.77,25.28 56.44,25.28 55.7,24.55 55.7,22.49 55.46,22.25 55.02,22.25 54.72,22.55 v2(54.72,22.84)
  L10_SIGNAL w0.203: v3(102.66,32.66) 102.03,32.66 100.84,31.47 v3(100.84,24.91)
SDIO_3P3: length 162.5
  TOP w0.127: U101.J4 54.01,47.18 v3(54.01,43.65)
  TOP w0.203: U25.18 31.1,52.65 31.37,52.92 v3(31.37,53.81) ; U13.12 107.06,38.06 v3(108.08,37.04) ; U16.30 v3(15.76,19.4)
  L3_SIGNAL w0.203: v1(36.45,38.95) 37.01,39.51 41.35,39.51 43.43,37.43 51.43,37.43 52.32,38.31 52.32,41.96 v3(54.01,43.65) 81.66,43.65 83.26,42.05 89.61,42.05 90.24,41.42 93.19,41.42 94.41,42.63 100.84,42.63 101.57,41.9 106.01,41.9 107.57,40.35 107.57,37.55 v3(108.08,37.04)
  L10_SIGNAL w0.203: v3(31.37,53.81) 34.04,51.14 34.04,40.22 35.33,38.93 36.43,38.93 v1(36.45,38.95) 36.45,38.31 35.31,37.17 35.31,36.28 32.43,33.41 32.43,25.19 32.77,24.85 32.77,19.9 29.34,16.47 v3(29.34,13.17)
  BOTTOM w0.203: v1(36.45,38.95) 36.85,38.55 U18.2 ; v3(15.76,19.4) 16.37,19.4 23.11,12.66 23.11,10.25 23.88,9.49 29.08,9.49 29.97,10.37 29.97,11.26 29.34,11.9 v3(29.34,13.17)
SDIO_CTRL_FMC: length 27
  TOP w0.203: U14.4 v3(105.63,35.14) 105.66,35.14 106.55,36.03 106.55,36.41 106.32,36.64 U13.10
  L10_SIGNAL w0.203: v1(90.14,43.32) 89.92,43.1 89.92,37.68 92.46,35.14 v3(105.63,35.14)
  BOTTOM w0.203: P1.H13 v1(90.14,43.32)
SDIO_FMC: length 21.6
  TOP w0.203: U14.2 106.3,32.73 v3(106.55,32.98) ; v3(102.49,37.68) 102.87,38.06 U13.5
  L3_SIGNAL w0.203: v3(106.55,32.98) 107.06,32.98 107.44,33.36 107.44,36.16 105.92,37.68 v3(102.49,37.68)
  L10_SIGNAL w0.203: v1(95.87,42.05) 95.87,41.76 96.39,41.24 99.29,41.24 101.22,39.3 101.22,38.58 102.12,37.68 v3(102.49,37.68)
  BOTTOM w0.203: P1.C15 v1(95.87,42.05)
SERDIN0_N: length 56.9
  TOP w0.254: v1(84.84,37.81) 84.84,32.98 78.49,26.63 77.92,26.63 58.71,26.63 58.43,26.35 58.05,26.35 57.77,26.63 57.42,26.63 57.15,26.36 56.77,26.36 56.5,26.63 56.15,26.63 55.58,26.06 55.58,25.69 55.33,25.45 54.96,25.45 54.7,25.18 54.7,24.28 54.72,24.26 U1.K15
  BOTTOM w0.254: C174.1 84.5,54.19 84.33,54.02 84.33,51.53 84.75,51.11 84.75,37.9 v1(84.84,37.81)
SERDIN0_P: length 56.3
  TOP w0.254: U1.J15 54.22,24.26 54.24,24.28 54.24,25.37 55.96,27.09 78.11,27.09 78.11,27.09 78.3,27.09 84.38,33.17 84.38,37.63 v1(84.2,37.81)
  BOTTOM w0.254: v1(84.2,37.81) 84.29,37.9 84.29,50.93 83.87,51.34 83.87,54.02 83.86,54.03 C173.1
SERDIN1_N: length 44
  TOP w0.254: U1.N15 56.22,24.26 56.2,24.28 56.2,24.78 56.45,25.03 79.17,25.03 84.52,30.38 96.93,30.38 C166.1
SERDIN1_P: length 44.8
  TOP w0.254: U1.M15 55.72,24.26 55.74,24.28 55.74,24.97 56.26,25.49 78.98,25.49 84.33,30.83 96.93,30.83 C165.1
SERDIN2_N: length 42.6
  TOP w0.254: U1.R12 57.26,22.39 81.99,22.39 84.89,25.29 96.32,25.29 97.6,26.57 98.06,26.57 C176.1
SERDIN2_P: length 42.6
  TOP w0.254: U1.R13 81.8,22.84 84.7,25.75 96.13,25.75 97.42,27.03 98.06,27.03 C175.1
SERDIN3_N: length 41.1
  TOP w0.254: U1.R9 57.26,20.89 82.78,20.89 83.38,21.49 98,21.49 C168.1
SERDIN3_P: length 41.1
  TOP w0.254: C167.1 98,21.95 83.19,21.95 82.59,21.34 U1.R10
SERDIN4_N: length 38.5
  TOP w0.254: U1.R7 83.47,19.84 84.15,20.52 95.38,20.52 C172.1
SERDIN4_P: length 39.1
  TOP w0.254: U1.R6 57.26,19.39 58.02,19.39 58.21,19.19 58.59,19.19 58.78,19.39 59.16,19.39 59.35,19.19 59.8,19.19 59.99,19.39 60.43,19.39 60.62,19.19 61.13,19.19 61.32,19.39 61.83,19.39 62.02,19.19 62.46,19.19 62.66,19.39 83.66,19.39 84.34,20.06 95.38,20.06 C171.1
SERDIN5_N: length 39.5
  TOP w0.254: U1.R4 96.69,18.34 C178.1
SERDIN5_P: length 40.1
  TOP w0.254: C177.1 96.69,17.89 61.51,17.89 61.3,17.67 60.88,17.67 60.66,17.89 60.24,17.89 60.03,17.67 59.61,17.67 59.39,17.89 58.94,17.89 58.72,17.67 58.3,17.67 58.08,17.89 57.26,17.89 U1.R3
SERDIN6_N: length 40.3
  TOP w0.254: U1.N1 56.2,16.82 56.2,15.9 56.46,15.64 95.42,15.64 C180.1
SERDIN6_P: length 41.1
  TOP w0.254: C179.1 95.42,15.18 56.27,15.18 55.74,15.71 55.74,16.82 U1.M1
SERDIN7_N: length 44.5
  TOP w0.254: U1.K1 54.69,16.81 54.69,15.4 55.98,14.11 79.36,14.11 80.37,13.1 96.69,13.1 C170.1
SERDIN7_P: length 45.2
  TOP w0.254: U1.J1 54.24,16.83 54.24,15.21 55.79,13.66 79.17,13.66 80.18,12.64 96.69,12.64 C169.1
SPI25_DAC: length 69.3
  TOP w0.508: v3(17.53,41.71) C89.1 18.67,43.61 E14.2
  L3_SIGNAL w0.203: v1(21.72,25.87) 24.51,25.87 25.84,24.54 30.03,24.54 30.99,23.58 35.94,23.58 v1(36.32,23.96) 37.21,24.85 43.81,24.85 45.47,23.2 49.66,23.2 50.29,22.57 50.29,20.66 51.69,19.26 51.69,18.76 52.07,18.38 54.48,18.38 54.72,18.14 v2(54.72,17.84)
  L10_SIGNAL w0.127: v2(54.72,17.84) 54.86,17.7 54.86,16.98
  L10_SIGNAL w0.203: v1(54.23,12.91) 54.61,13.3 54.61,16.72 54.86,16.98 ; v3(17.53,41.71) 18.03,41.2 18.03,29.55 v1(21.72,25.87)
  BOTTOM w0.203: R43.1 36.12,23.2 36.32,23.4 v1(36.32,23.96) ; v1(54.23,12.91) 53.85,12.53 53.85,11.77 53.59,11.52 R6.2
  BOTTOM w0.305: v2(54.72,17.84) 54.72,17.97 54.71,17.98 54.71,18.34 R5.1
SUPPLY1P2: length 63.9
  TOP w0.203: U26.3 v3(107.52,13.3)
  TOP w0.305: 70.81,10.5 C69.2 ; C69.2 71.82,9.34 ; C69.2 71.82,11.66 ; 71.68,6.36 71.86,6.18 v3(76.33,6.18) ; C72.2 71.82,8.86 ; C72.2 71.82,6.55 ; C72.2 70.81,7.71
  L3_SIGNAL w0.305: v3(107.52,13.3) 107.03,13.3 105.45,14.88 102.66,14.88 102.1,14.31 99.19,14.31 98.3,15.2 79.24,15.2 77.46,13.42 72.9,13.42 v3(70.48,11.01)
  BOTTOM w0.305: v3(76.33,6.18) 76.86,6.18 76.98,6.31 U6.6
  BOTTOM w0.406: 70.43,13.38 E5.2 71.12,12.84
  BOTTOM w0.508: 70.81,7.71 C72.2 ; C72.2 71.82,6.55 ; C72.2 71.82,8.86 ; v3(47.88,29.81) E7.1 48.96,28.73 v3(48.77,28.54) ; 71.82,9.34 C69.2 ; C69.2 71.82,11.66 ; C69.2 70.81,10.5
  vias: v3(52.32,36.92) v3(52.32,36.28) v3(52.32,35.65) v3(52.83,36.92) v3(52.83,36.28) v3(52.83,35.65) v3(70.48,10.12) v3(70.48,8.22) v3(70.48,7.33) v3(70.87,9.1) v3(71.75,9.1)
SUPPLY1P75: length 53.9
  TOP w0.203: R120.1 87.5,64.92 87.5,63.84 ; VR2.4 86.78,64.56 87,64.35 87,63.84
  TOP w0.254: v3(76.45,38.57) 76.45,38.56 R18.2
  TOP w0.305: VR2.3 86.47,63.91 ; 77.74,41.62 R36.2 77.08,40.96 ; 84.67,60.81 VR2.16 85.2,61.69 ; R82.2 65.28,31.84 v3(66.17,32.73) ; 86.47,62.61 VR2.1 85.59,62.08 ; C206.1 87.12,61.52 v3(87.12,62.32) ; 84.02,60.81 VR2.15 ; VR2.2 86.47,63.26
  TOP w0.635: 87.5,62.04 C206.1 86.55,61.14
  TOP w0.762: 80.9,40.4 C54.2 79.74,39.39 ; C53.2 79.26,39.39 ; C53.2 76.95,39.39 ; C53.2 78.11,40.4
  BOTTOM w0.305: U27.15 63.44,34.87 ; R118.1 75.56,65.87 75.18,66.25 72.39,66.25 ; U27.4 65.7,31.12 65.91,31.33 65.91,31.71 ; 64.63,33.99 U27.16 64.09,34.87 ; 72.39,65.75 72.52,65.62 73.03,65.62 73.24,65.42 VR1.4 ; 39.51,9.72 U28.4 39,10.52 ; 41.02,9.49 41.53,9.49 41.76,9.72 U28.16 ; 40.01,9.72 U28.3 ; 65.9,33.07 U27.1 65.02,33.6 ; U27.2 65.9,32.42 ; 40.51,9.72 U28.2 ; 41.01,9.72 U28.1 ; U27.3 65.9,31.77
  BOTTOM w0.635: 66.38,31.77 C194.1 67.18,32.51 ; 39.78,8.09 C95.1 40.68,9.04
  BOTTOM w0.762: C51.2 80.26,40.36 ; C51.2 78.9,39.2 ; C51.2 81.62,39.2
  BOTTOM w1.016: 77.33,38.81 L5.2 ; L5.2 78.12,41.11 ; L5.2 77.33,43.41
  vias: v3(38.86,8.98) v3(38.86,8.34) v3(39.5,8.98) v3(39.5,8.34) v3(66.17,33.36) v3(66.8,33.36) v3(66.8,32.73) v3(68.96,64.86) v3(69.72,64.86) v3(70.48,64.86) v3(70.74,66.13) v3(71.5,66.13) v3(72.26,66.13) v3(78.48,41.62) v3(78.48,41.11) v3(78.48,40.6) v3(78.99,41.62) v3(78.99,41.11) v3(78.99,40.6) v3(79.5,41.62) v3(79.5,41.11) v3(79.5,40.6) v3(80.01,41.11) v3(80.01,40.6) v3(86.36,61.56) v3(86.36,60.92) v3(87.76,62.32)
SUPPLY3P3: length 48.9
  TOP w0.254: C125.2 105.28,41.23 U13.16 ; U23.14 105.28,54.81 C103.2
  TOP w0.305: C125.2 105.93,41.88 v3(105.93,42.51) ; v3(105.94,56.09) 105.94,55.47 C103.2 ; U20.7 68.19,36.15 68.45,36.41 ; 66.98,37.16 U20.8 67.76,36.65
  TOP w0.508: 47.88,39.81 E16.1 48.87,38.89 ; C243.1 68.81,38.95 ; C243.1 67.91,38 ; C243.1 67.91,39.9 ; 49.17,38.89 E26.1 50.16,39.81
  TOP w1.016: E3.2 87.31,5.71 ; E3.2 88.24,4.72 ; E3.2 87.31,3.73
  BOTTOM w0.203: R126.1 33.29,49.49 33.29,48.59 33.53,48.34 VR3.4
  BOTTOM w0.254: 68.19,25.84 U9.A1 68.55,25.48 ; U9.B1 68.55,24.98
  BOTTOM w0.305: 34.29,3.01 34.56,3.27 U7.8 ; 34.46,43.16 VR3.16 33.92,44.03 ; 32.66,45.61 VR3.2 ; 32.66,44.96 VR3.1 ; 32.66,46.26 VR3.3 ; v3(27.81,23.84) C100.1 27.24,23.26 27.17,23.19 U22.10 ; 35.11,43.16 VR3.15 ; 32.66,46.91 VR3.4
  BOTTOM w0.381: R33.1 v3(26.42,35.52) R10.1
  BOTTOM w0.508: v3(26.96,32.6) 26.96,31.49 C18.1 24.74,31.46 Y1.6 ; C70.1 70,25.09 ; C70.1 68.94,25.09 ; C70.1 69.47,25.63 ; v3(30.99,2.12) 31.84,2.12 C63.1 32.04,3.01 v3(30.99,3.01) ; v3(29.84,23.96) R92.1 ; R53.1 v3(23.75,23.46) ; v3(24.26,18.63) 23.75,19.14 R54.1 ; R52.1 v3(24.89,24.22)
  BOTTOM w0.635: 26.03,44.44 E27.1 25.04,45.36 ; 31.37,45.32 C244.1 32.32,46.23
  BOTTOM w0.762: C63.1 33.95,2.67 34.29,3.01
  vias: v3(24.64,45.55) v3(24.64,44.66) v3(25.4,44.16) v3(26.42,44.16) v3(31.11,44.92) v3(31.75,44.92) v3(31.75,44.28) v3(32.38,44.92) v3(49.66,40.73) v3(49.66,40.09) v3(50.29,40.73) v3(50.29,40.09) v3(67.31,40.22) v3(67.94,40.22) v3(68.58,40.22) v3(69.22,40.22) v3(71.5,24.09) v3(72.14,24.09) v3(87,6.56) v3(87,5.93) v3(87,3.52) v3(87,2.88) v3(87.63,6.56) v3(87.63,5.93) v3(87.63,3.52) v3(87.63,2.88)
SUPPLY5P5: length 48.8
  TOP w0.305: C139.1 22.82,40.98 v3(21.97,40.98) ; C139.1 22.9,40.22 v3(21.97,40.22) ; C139.1 23.54,40.86 U12.7 ; C139.1 23.44,40.36 U12.8 ; U17.5 34.17,59.57 34.48,59.27 35.34,59.27 35.6,59.02 ; 35.68,59.28 35.17,59.78 U17.7 ; 35.68,59.28 U17.8 ; 35.68,59.28 35.68,59.19 C142.1 ; 23.27,28.4 C140.1 23.32,28.29 U15.8 ; 23.27,28.4 23.27,29.47 23.58,29.79 U15.5 ; 23.27,28.4 23.66,28.79 U15.7 ; U10.5 5.32,15.06 4.95,14.69 4.95,14.06 U10.7 ; 6.04,13.05 U10.8 5.27,13.56
  TOP w0.508: v3(35.31,58) 35.31,58.72 C142.1 36.07,58.8 v3(36.07,58) ; R50.2 v3(21.84,28.79) 22.82,28.79 C140.1 22.9,28.03 v3(21.84,28.03)
  TOP w0.635: 4.76,13.84 C99.1 3.81,12.94
  TOP w0.762: 22.48,56.21 C45.2 ; C45.2 23.84,57.36 ; C45.2 21.12,57.36 ; 16.38,56.21 C43.2 ; C43.2 15.02,57.36 ; C43.2 17.74,57.36 ; C50.2 20.79,57.36 ; C50.2 18.07,57.36 ; C50.2 19.43,56.21 ; 24.67,57.36 L4.2 25.42,56
  BOTTOM w0.305: R20.2 v3(24.26,57.11)
  vias: v3(3.56,12.66) v3(4.32,12.66) v3(16.51,55.84) v3(17.14,55.84) v3(17.78,55.84) v3(18.41,55.84) v3(19.05,55.84) v3(19.69,55.84)
SUPPLYN2P8: length 11.4
  TOP w0.305: C316.1 59.92,2.9 U21.6 57.55,2.9 57.15,2.5 U21.PAD
  TOP w0.508: v3(60.32,1.36) v3(60.32,1.99) 60.32,2.79 60.24,2.88 ; R65.1 R19.2
  TOP w0.635: C316.1 60.24,2.88 R19.2
  BOTTOM w0.508: 60.05,2.75 L6.2 59.18,2.08
  BOTTOM w0.762: 61.66,1.09 C52.2 60.65,2.25
SVPLL12_DAC: length 35.8
  TOP w0.254: U1.N9 v2(56.22,20.34)
  L10_SIGNAL w0.305: v2(56.22,20.34) 56.22,20.62 56.39,20.79 58.04,20.79
  L10_SIGNAL w0.508: v3(53.59,2.25) 56.01,4.66 59.05,4.66 60.45,6.06 60.45,11.9 63.12,14.57 63.12,17.61 60.83,19.9 59.56,19.9 58.67,20.79 58.04,20.79
  BOTTOM w0.508: v3(53.59,2.25) 53.59,2.74 C339.1 54.5,4.94 C312.1
  BOTTOM w0.762: C312.1 54.1,5.33 E8.2
SVSYNC33_DAC: length 6.1
  TOP w0.305: TP6.1 v3(61.21,29.81)
  BOTTOM w0.762: C88.1 60.36,23.84 v3(59.44,23.84) v3(58.8,23.84)
  BOTTOM w1.016: E13.2 61.98,25.61 60.62,24.26 C88.1
  vias: v2(56.72,23.34) v2(56.72,17.34)
SW_2165: length 12.7
  TOP w0.203: v3(77.34,11.9) 76.49,11.9 C61.1
  BOTTOM w0.203: R21.1 77.85,17.61
  BOTTOM w0.305: U6.15 77.98,11.7 ; U6.16 78.48,11.7 ; v3(77.34,11.9) 77.48,11.76 U6.14 ; U6.17 78.98,13.41
  BOTTOM w0.762: 77.7,12.74 L8.1 ; L8.1 78.55,14.69 ; L8.1 77.7,16.65
SYNC_2370: length 159.6
  TOP w0.203: v3(21.94,62.95) U3.4
  L3_SIGNAL w0.203: v3(21.94,62.95) 22.7,62.19 24.89,62.19 26.03,61.05 37.72,61.05 38.35,60.41 39.5,60.41 43.81,64.73 53.85,64.73 54.61,65.49 67.18,65.49 68.96,67.27 v3(80.52,67.27) ; v3(103.25,25.61) 103.25,28 102.15,29.1 101.14,29.1 100.81,28.78 92.19,28.78 86.23,22.82 81.21,22.82 v3(80.01,24.02)
  BOTTOM w0.203: v3(80.52,67.27) 80.9,66.89 85.85,66.89 89.34,63.4 99.88,63.4 101.98,61.3 101.98,55.71 103.12,54.57 103.12,51.65 102.62,51.14 102.62,50.25 101.85,49.49 101.85,35.9 102.63,35.13 102.63,33.45 103.25,32.83 v3(103.25,25.61) ; R26.2 v3(80.01,24.02) 80.01,21.61 R24.2
SYNC_2384: length 11.5
  BOTTOM w0.203: R23.2 76.14,21.49 74.68,22.95 74.68,28.92 75.2,29.44 U2.23
SYNC_5073: length 21.9
  TOP w0.203: v3(61.59,10.88) 62.36,10.12 R27.1
  L3_SIGNAL w0.203: v3(69.98,16.72) 67.31,14.06 66.42,14.06 62.67,10.3 62.17,10.3 v3(61.59,10.88)
  BOTTOM w0.203: v3(69.98,16.72) 72.26,19.01 R25.2 ; v3(61.59,10.88) 62.35,11.63 U5.4
SYNC_DAC_N: length 47.5
  TOP w0.127: R81.1 88.01,49.36 86.3,49.36 v1(86.02,49.08)
  L10_SIGNAL w0.127: v2(56.22,21.84) 56.34,21.96 57.05,21.96 57.66,22.57 57.96,22.57 58.27,22.26 58.57,22.26 58.88,22.57 60.2,22.57 64.77,27.14 64.77,33 81.18,49.41 85.69,49.41 v1(86.02,49.08)
SYNC_DAC_P: length 47.2
  TOP w0.127: R80.1 88.02,49.61 86.3,49.61 v1(86.02,49.89)
  L10_SIGNAL w0.127: v1(86.02,49.89) 85.8,49.67 81.08,49.67 64.52,33.11 64.52,27.24 60.09,22.82 57.55,22.82 56.95,22.21 56.35,22.21 v2(56.22,22.34)
TXEN: length 83.9
  TOP w0.203: v3(106.93,43.78) 107.31,44.16 107.31,44.66 107.05,44.93 U24.10
  L3_SIGNAL w0.203: v3(106.81,21.3) 106.81,19.77 105.21,18.18 88.18,18.18 86.59,19.77 85.98,19.77 84.33,18.12 57.63,18.12 57.18,17.66 57.18,17.16 56.86,16.84 54.22,16.84 v2(53.72,17.34)
  L10_SIGNAL w0.203: v3(106.93,43.78) 107.61,43.1 107.61,39.64 106.93,38.96 106.93,36.28 107.44,35.77 107.44,34.25 107.06,33.87 107.06,28.66 106.05,27.65 106.05,22.06 v3(106.81,21.3)
TXEN_FMC: length 14.5
  TOP w0.203: v3(102.49,44.28) 103.13,44.93 U24.5
  L3_SIGNAL w0.203: v1(90.77,43.32) 91.35,43.9 98.55,43.9 99.19,44.54 102.23,44.54 v3(102.49,44.28)
  BOTTOM w0.203: P1.G13 v1(90.77,43.32)
UNNAMED_14_ADP216X_I57_AVIN: length 4.2
  BOTTOM w0.305: C58.2 81.87,8.6 U6.22
  BOTTOM w0.508: R28.2 82.75,7.72 C58.2
UNNAMED_14_ADP216X_I57_COMP: length 4.1
  BOTTOM w0.203: C60.1 77.06,4.9 R29.1 77.48,4.76 U6.5
UNNAMED_14_ADP216X_I57_SS: length 2.9
  BOTTOM w0.203: U6.4 77.98,5.93 79.29,4.62 C55.2
UNNAMED_14_ADP216X_I57_SYNC: length 1.6
  TOP w0.203: R22.1 79.47,6.85 v3(80.23,6.85)
  BOTTOM w0.203: U6.1 v3(80.23,6.85)
UNNAMED_14_ADP237X_I39_EN: length 3.3
  TOP w0.203: U3.3 21.21,64.1 v3(20.95,63.84)
  BOTTOM w0.203: R68.2 21.09,64.87 C73.1 v3(20.95,63.84)
UNNAMED_14_ADP237X_I39_FB: length 6.4
  TOP w0.203: v3(24.89,62.95) 24.89,63.47 25.02,63.6 U3.5
  BOTTOM w0.203: R4.1 23.11,60.88 23.11,61.43 23.75,62.06 24.98,62.06 ; 24.98,62.06 R3.2 ; 24.98,62.06 24.89,62.15 v3(24.89,62.95) 24.89,63.83 C29.2
UNNAMED_14_ADP237X_I39_SW: length 2
  TOP w0.305: 26.77,65.34 26.03,64.6 U3.7
UNNAMED_14_ADP238X_I1_COMP: length 3.2
  BOTTOM w0.305: C35.1 71.95,30.64 R14.1 73.03,30.69 73.68,31.35 U2.1
UNNAMED_14_ADP238X_I1_RT: length 3.2
  BOTTOM w0.254: R2.2 75.32,28.93 75.7,29.3 U2.22
UNNAMED_14_ADP238X_I1_SS: length 3.3
  BOTTOM w0.254: U2.24 74.7,29.79 73.62,28.71 C26.1
UNNAMED_14_ADP238X_I1_SW1: length 16.8
  TOP w0.203: v3(74.04,35.39) 74.46,35.39 C39.1
  BOTTOM w0.305: U2.7 74.7,33.96 74.8,33.85 ; U2.7 74.19,34.65 ; U2.7 74.7,35.25 74.42,35.52 ; U2.PAD2 75.57,33.85 74.8,33.85 ; U2.PAD2 75.82,33.35 U2.5 72.53,33.35 72.39,33.49 ; U2.PAD2 76.07,33.35 U2.14 ; U2.6 73.9,34.36 ; U2.6 74.8,33.85 ; U2.6 73.1,33.85
  BOTTOM w1.016: 72.56,35.05 L3.1 70.36,33.96
UNNAMED_14_ADP238X_I1_VREG: length 2.1
  BOTTOM w0.254: C31.1 72.33,32.14 72.95,32.14 73.28,32.35 U2.3
UNNAMED_14_ADP5073_I95_COMP: length 3.6
  BOTTOM w0.203: R1.2 65.79,14.57 C24.1 65.4,14.18 U5.7
UNNAMED_14_ADP5073_I95_FB: length 15.8
  TOP w0.203: v3(63.37,8.72) 62.73,8.08 R19.1
  L10_SIGNAL w0.203: v3(66.93,12.38) 64.37,12.38 63.37,11.39 v3(63.37,8.72)
  BOTTOM w0.203: U5.8 v3(66.93,12.38) 66.93,13.04 67.42,13.54 R39.2
UNNAMED_14_ADP5073_I95_SS: length 2.3
  BOTTOM w0.203: U5.5 64.4,13.41 63.5,14.31 R17.2
UNNAMED_14_ADP5073_I95_SW: length 4.9
  BOTTOM w0.305: 59.98,6.65 D2.C 59.31,7.18 ; 62.69,9.94 62.88,10.13 U5.1 63.65,9.62
  BOTTOM w0.762: 60.6,7.2 L1.2 61.47,8.44
UNNAMED_14_ADP5073_I95_VREF: length 2.5
  BOTTOM w0.203: U5.9 67.32,11.63 67.44,11.52 C46.1 68.08,12.53 R39.1
UNNAMED_14_ADP5073_I95_VREG: length 7
  TOP w0.203: R13.2 63.87,12.03 65.9,12.03 C47.1 67.3,10.63 v3(68.2,10.63)
  BOTTOM w0.203: U5.11 68.19,10.63 v3(68.2,10.63)
UNNAMED_14_CAP_I5_N1: length 5.8
  TOP w0.254: R16.1 C40.1 74.28,37.18 74.79,36.68 R18.1
UNNAMED_14_CAP_I5_N2: length 12.1
  TOP w0.254: C40.2 v3(72.4,39.07)
  BOTTOM w0.762: 73.1,37.04 C42.2 74.1,38.2
  BOTTOM w1.016: 73.01,41.11 L5.1 ; L5.1 73.8,38.81 ; L5.1 73.8,43.41 ; 70.36,38.61 L3.2 72.56,37.51
UNNAMED_14_CAP_I30_N1: length 1.6
  BOTTOM w0.305: R14.2 69.56,30.69 C37.1
UNNAMED_14_CAP_I41_N2: length 6.9
  TOP w0.762: C38.2 29.35,60.41 ; C38.2 28.19,59.05 ; C38.2 28.19,61.77 ; 27.41,58.72 L4.1 28.16,57.36
  BOTTOM w0.203: C33.2 27.05,62.19 v3(27.3,61.94)
UNNAMED_14_CAP_I52_N1: length 13
  BOTTOM w0.203: R4.2 25.95,58.67 27.81,60.54 27.81,63.71 27.56,63.97 C33.1 26.92,63.84 C29.1
  BOTTOM w0.305: R4.2 22.11,58.18 R20.1
UNNAMED_14_CAP_I60_N2: length 8
  BOTTOM w0.406: E5.1 71.81,14.22 ; E5.1 70.43,14.22 ; E5.1 71.12,14.77
  BOTTOM w0.508: 73.28,16.01 C62.2 ; C62.2 72.12,15.01 ; C62.2 74.44,15.01
  BOTTOM w0.762: 74.86,14.69 L8.2 75.71,16.65
UNNAMED_14_CAP_I75_N1: length 1.5
  BOTTOM w0.203: C64.1 77.3,2.88 R29.2
UNNAMED_14_CAP_I121_N1: length 1
  BOTTOM w0.203: R1.1 C28.1
UNNAMED_14_CAP_I152_N2: length 3.7
  BOTTOM w0.305: 59.98,5.97 D2.A 59.31,5.44
  BOTTOM w0.508: 59.18,4.7 L6.1 60.05,4.02
  BOTTOM w1.016: C48.2 60.65,4.41
UNNAMED_14_DIOLED_I89_N: length 2.1
  TOP w0.203: Q1.3 71.17,2.25 DS2.C
UNNAMED_14_DIOLED_I89_P: length 1.4
  TOP w0.203: R32.2 73.27,2.12 DS2.A
UNNAMED_14_RES_I86_N2: length 1.4
  TOP w0.203: R31.2 68.14,3.77 Q1.1
UNNAMED_14_RES_I176_N1: length 3.1
  BOTTOM w0.203: R24.1 77.93,19.84 R21.2 77.71,19.9 R23.1 R25.1
UNNAMED_15_AD9162V4_I79_ISET: length 2.7
  TOP w0.203: U1.A15 50.22,25.95 R7.1
UNNAMED_15_AD9162V4_I79_PLLLDOB: length 2.1
  BOTTOM w0.203: C6.1 58.31,20.79 57.17,20.79 v2(56.72,20.34)
UNNAMED_15_AD9162V4_I79_RESETN: length 0.6
  BOTTOM w0.305: R5.2 54.04,18.03 v2(54.22,17.84)
UNNAMED_15_AD9162V4_I79_SYSREF: length 1
  TOP w0.254: U1.N4 v2(55.84,18.34)
  BOTTOM w0.254: C44.2 56.13,18.35 55.85,18.35 v2(55.84,18.34)
UNNAMED_15_AD9162V4_I79_SYSREF_: length 0.9
  TOP w0.254: U1.N5 v2(55.84,18.84)
  BOTTOM w0.254: C104.2 v2(55.84,18.84)
UNNAMED_15_AD9162V4_I79_VBGNEG: length 0.4
  BOTTOM w0.254: C8.1 51.22,22.42 v2(51.22,22.34)
UNNAMED_15_AD9162V4_I79_VREF: length 2.6
  TOP w0.203: U1.B15 50.72,26.31 C10.1
UNNAMED_15_DIOLED_I23_P: length 1.7
  BOTTOM w0.203: CR5.A 51.56,12.63 51.56,12.04 R6.1
UNNAMED_21_ADL5240_I13_AMPIN: length 3.5
  TOP w0.203: 22.73,21.42 22.71,21.4 U16.15
  TOP w0.686: C149.2 22.73,21.42
UNNAMED_21_ADL5240_I13_AMPOUT: length 5.7
  TOP w0.305: 22.61,17.87 22.61,18.63 22.35,18.88 22.35,18.9 U16.10
  TOP w0.508: C7.2 21.82,16.09 L7.1 22.61,16.57 22.61,17.87
UNNAMED_21_ADL5240_I13_DSAIN: length 1.7
  TOP w0.305: U16.4 19.05,16.35 C7.1
UNNAMED_21_ADL5240_I13_DSAOUT: length 11.1
  TOP w0.203: U16.21 19.05,23.71
  TOP w0.686: C19.1 17.53,25.23 arc(18.61,24.79) 19.05,23.71
UNNAMED_21_CAP_I99_N2: length 7.6
  TOP w0.686: J4.1 C19.2
UNNAMED_21_CAP_I102_N1: length 2.2
  TOP w0.686: C2.1 T1.3
UNNAMED_21_CAP_I102_N2: length 2.7
  TOP w0.203: 36.96,21.42 R71.1
  TOP w0.686: C2.2 R77.1
UNNAMED_21_CNBNC3P_I104_CNTR: length 12.6
  TOP w0.686: C155.1 J5.1
UNNAMED_21_FLTRBP4P_I97_IN: length 3
  TOP w0.203: R78.1 33.4,21.42
  TOP w0.686: FL1.1 R77.2
UNNAMED_21_FLTRBP4P_I97_OUT: length 2.1
  TOP w0.686: FL1.3 C149.1
UNNAMED_22_ADM1184_I145_OUT1: length 2.5
  BOTTOM w0.203: R52.2 25.47,21.87 25.47,21.87 25.55,21.8 U22.9
UNNAMED_22_ADM1184_I145_VIN1: length 4.3
  BOTTOM w0.203: U22.2 32.25,21.8 33.02,22.57 R91.2 32.06,23.65 R92.2
UNNAMED_22_ADM1184_I145_VIN2: length 4.3
  BOTTOM w0.203: U22.3 32.64,21.3 33.4,22.06 R44.1 R43.2
UNNAMED_22_ADM1184_I145_VIN3: length 4
  BOTTOM w0.203: U22.4 34.18,20.8 R45.2 R46.1
UNNAMED_22_ADM1184_I145_VIN4: length 4.6
  BOTTOM w0.203: U22.5 31.99,20.3 33.66,18.63 R48.2 R49.1
UNNAMED_22_ADM7154_I195_BYP: length 3.5
  BOTTOM w0.305: C66.2 37.07,7.33 35.81,7.33 35.56,7.07 U7.3
UNNAMED_22_ADM7154_I195_REF: length 3.3
  BOTTOM w0.305: U7.6 35.56,2.5 35.94,2.12 C74.1 36.06,2.14 U7.5
UNNAMED_22_ADM7154_I195_VOUT: length 4.1
  BOTTOM w0.305: 35.06,7.7 U7.2
  BOTTOM w0.635: 35.06,7.7 35.06,8.12 C77.1
  BOTTOM w0.762: E12.1 34.84,10.42 C77.1
UNNAMED_22_ADM7154_I195_VREG: length 2.6
  BOTTOM w0.305: U7.1 34.56,6.68 34.29,6.95 32.6,6.95 C68.1
UNNAMED_22_ADM7170_I342_SENSE: length 8.3
  TOP w0.203: 9.93,13.95 9.93,14.42 9.78,14.56 U10.3
  TOP w0.305: 9.72,13.56 U10.1 8.94,13.05 ; U10.2 9.72,14.06
  TOP w0.635: C101.1 12.13,13.84 ; C101.1 11.18,12.94 ; C101.1 10.22,13.84
  TOP w0.762: 13.59,12.69 E15.1 12.6,13.61
UNNAMED_22_ADP176X_I393_PG: length 1.8
  BOTTOM w0.203: U28.15 42.41,11.78 43.12,11.07 R85.2
UNNAMED_22_ADP176X_I393_REFCAP: length 2.1
  TOP w0.203: C310.2 37.72,10.01 v3(37.72,10.88)
  BOTTOM w0.203: U28.5 38.11,11.28 v3(37.72,10.88)
UNNAMED_22_ADP176X_I393_SS: length 2.1
  BOTTOM w0.203: C86.1 43.77,12.28 U28.14
UNNAMED_22_ADP176X_I393_VADJ: length 1.7
  BOTTOM w0.203: R84.2 37.48,13.3 37.97,13.3 38.49,12.78 U28.8
UNNAMED_22_ADP176X_I393_VREG: length 1.8
  TOP w0.203: v3(37.72,11.78) 37.72,12.52 C334.2
  BOTTOM w0.203: U28.6 v3(37.72,11.78)
UNNAMED_22_ADP196_I267_VOUT1: length 4.9
  BOTTOM w0.203: U9.A2 67.7,25.99
  BOTTOM w0.254: 67.34,24.98 U9.B2 U9.A2 67.34,25.48
  BOTTOM w0.508: C80.1 66.83,25.35 ; C80.1 65.76,25.35 ; C80.1 66.29,25.88
  BOTTOM w0.635: 65,25.61 E13.1 64.22,26.44
UNNAMED_22_ADP1740_I381_N5: length 3.3
  TOP w0.203: R82.1 v3(65.28,30.06) 65.66,29.68 65.98,29.68 R83.2
  BOTTOM w0.203: U27.5 64.76,30.19 64.9,30.06 v3(65.28,30.06)
UNNAMED_22_ADP1740_I381_N7: length 2.6
  BOTTOM w0.203: C195.1 61.79,28.98 61.98,29.17 62.48,29.17 62.79,29.48 U27.7
UNNAMED_22_ADP7182V6_I320_VOUT: length 4.4
  TOP w0.305: 56.07,3.52 U21.1
  TOP w0.635: 56.07,3.52 55.79,3.79 C317.1 55.79,6.69 E21.1
UNNAMED_22_CAP_I259_N1: length 12.9
  TOP w0.508: TP7.1 v3(55.24,29.68)
  BOTTOM w0.508: 56.27,29.7 C91.1 56.27,27.47 E6.1
  BOTTOM w0.635: C91.1 55.61,29.04
  BOTTOM w0.762: 53.72,30.85 E4.2 ; E4.2 55.25,30.85 ; E4.2 54.48,30.05 ; 56.07,30.02 C82.1 55.33,30.82 ; 55.4,10.76 E9.1 ; E9.1 56.32,11.75 ; E9.1 56.32,9.76
  BOTTOM w0.889: 55.09,9.29 E8.1 54.1,10.22
  vias: v3(54.36,29.68) v3(54.36,29.04) v3(54.74,12.03) v3(55.24,29.04) v3(55.37,12.03) v3(56.01,12.03) v3(56.64,12.03)
